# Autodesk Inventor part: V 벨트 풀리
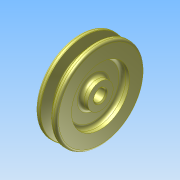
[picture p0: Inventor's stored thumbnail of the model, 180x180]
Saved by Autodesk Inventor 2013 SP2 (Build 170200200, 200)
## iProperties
Created: 2025-10
Part Number: V 벨트 풀리
Material: Generic
Document SubType Name: Modeling
Designer: a
Density: 1 g/cm^3
Author: a
변환 표준: STEP AP214IS
전처리기: Build: 200, Release: 2013 SP2 Update 6 - Date: Thu 07/17/2014
전송 단위: 밀리미터
불확실성: 0.01
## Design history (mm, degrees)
node "V 벨트 풀리1"
node "솔리드1"
node "기준1"
